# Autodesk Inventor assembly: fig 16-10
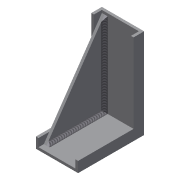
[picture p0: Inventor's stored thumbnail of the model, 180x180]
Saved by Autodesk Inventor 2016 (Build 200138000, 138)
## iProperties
Shininess: 64.0
Length Units: 11269
Angle Units: 11279
Time Units: 11290
Mass Units: 11283
Length Display Precision: 3
Angle Display Precision: 2
Compacted: True
Created: 2003-01
Part Number: fig 16-10
Document SubType Name: Weldment
Designer: Owner
Density: 0.0
Volumn: 0.0
Area: 0.0
PropertySet Name: Model Information
Control State: 0
Master: False
Checked Out: False
Author: Owner
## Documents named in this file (3)
- D:\KAVITA\Autodesk Inventor_ 2016 Project_Kavita\Inventor_Part Files\Inventor_2016_Part\c16_Inv_2016\c16_inv_2016_prt\fig 16-10\fig 16-10.iam
- D:\KAVITA\Autodesk Inventor_ 2016 Project_Kavita\Inventor_Part Files\Inventor_2016_Part\c16_Inv_2016\c16_inv_2016_prt\fig 16-10\Bracket-1.ipt
- D:\KAVITA\Autodesk Inventor_ 2016 Project_Kavita\Inventor_Part Files\Inventor_2016_Part\c16_Inv_2016\c16_inv_2016_prt\fig 16-10\Bracket-plate.ipt
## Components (2 placed, 2 different names)
1. Bracket-1:1 — Mate:1, Mate:2
2. Bracket-plate:1 — Mate:1, Mate:2
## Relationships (2: Mate 2)
- Mate:1: Bracket-1:1 ↔ Bracket-plate:1
- Mate:2: Bracket-1:1 ↔ Bracket-plate:1
